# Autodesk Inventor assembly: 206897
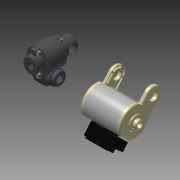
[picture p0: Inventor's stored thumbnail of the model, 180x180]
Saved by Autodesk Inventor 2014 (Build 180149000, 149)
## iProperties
Created: 2008-01
Part Number: 206897
Document SubType Name: Assembly
Designer: jjohnson
Mass: 119.186 g
Surface Area: 559.788 cm^2
Volume: 62.8758 cm^3
Density: 1.89557 g/cm^3
Author: jjohnson
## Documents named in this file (5)
- C:\Users\iTools\Desktop\tutorial files\Automotive\2000\206897.iam
- C:\Users\iTools\Desktop\tutorial files\Automotive\2000\200135.ipt
- C:\Users\iTools\Desktop\tutorial files\Automotive\2000\200678.ipt
- C:\Users\iTools\Desktop\tutorial files\Automotive\8000\801384.ipt
- C:\Users\iTools\Desktop\tutorial files\Automotive\9000\900402.iam
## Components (7 placed, 4 different names)
1. 200135:1 — Mate:1, Mate:12, Mate:3, Insert:1, Insert:2, Insert:3, Insert:4, Mate:11, Mate:10, Mate:9
2. AS 1427 - Metric M3 x 6:1 — Insert:1
3. AS 1427 - Metric M3 x 6:2 — Insert:2
4. AS 1427 - Metric M3 x 6:3 — Insert:3
5. AS 1427 - Metric M3 x 6:4 — Insert:4
6. 200678:1 — Mate:1, Mate:12, Mate:3
7. 900402:1 [sub-assembly] — Mate:11, Mate:10, Mate:9
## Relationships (10: Mate 6, Insert 4)
- Mate:1: 200135:1 ↔ 200678:1
- Mate:12: 200135:1 ↔ 200678:1
- Mate:3: 200135:1 ↔ 200678:1
- Insert:1: 200135:1 ↔ AS 1427 - Metric M3 x 6:1
- Insert:2: 200135:1 ↔ AS 1427 - Metric M3 x 6:2
- Insert:3: 200135:1 ↔ AS 1427 - Metric M3 x 6:3
- Insert:4: 200135:1 ↔ AS 1427 - Metric M3 x 6:4
- Mate:11: 200135:1 ↔ 900402:1
- Mate:10: 200135:1 ↔ 900402:1
- Mate:9: 200135:1 ↔ 900402:1
